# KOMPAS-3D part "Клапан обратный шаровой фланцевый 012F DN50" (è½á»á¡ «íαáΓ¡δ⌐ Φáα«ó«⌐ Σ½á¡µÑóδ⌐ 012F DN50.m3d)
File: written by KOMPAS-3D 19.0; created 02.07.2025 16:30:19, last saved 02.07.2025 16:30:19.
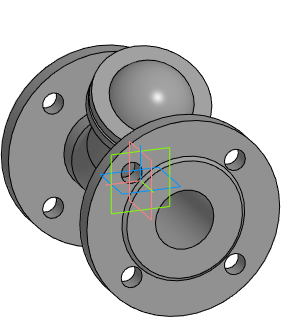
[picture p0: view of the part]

Document properties: Полное имя файла: E:\Dendor Работа Сачек\3D для проектировщиков\5.3 Тип 012F, 012F.Z Клапан обратный шаровой фланцевый\stp_Клапан обратный шаровой фланцевый 012F\Клапан обратный шаровой фланцевый 012F DN50.m3d

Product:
- Part/product: Клапан обратный шаровой фланцевый 012F DN50

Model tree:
1. Операция без истории:1  (labels: Клапан обратный шаровой фланцевый 012F DN50)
